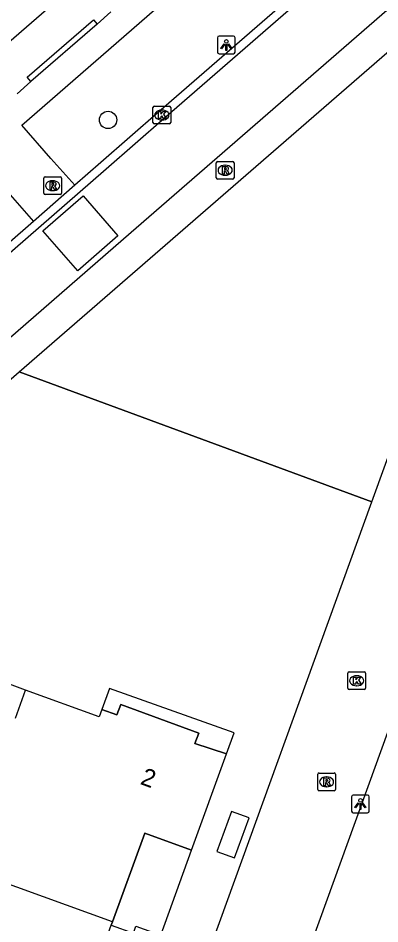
# Model space of a CAD drawing. Extents: x 155888 to 156864, y 383882 to 384671.
# Drawn here: x 156672 to 156692.5, y 384149.6 to 384200.8 of the extents above; entities that cross this region are included whole.
import ezdxf

# ---------------------------------------------------------------- set-up
doc = ezdxf.new("R2010")
doc.units = 0
for name, color, linetype in [('IMGEO_Boom', 7, 'Continuous'), ('IMGEO_Groenvoorziening', 7, 'Continuous'), ('IMGEO_Hek', 7, 'Continuous'), ('IMGEO_Kolk', 7, 'Continuous'), ('IMGEO_Lichtpunt', 7, 'Continuous'), ('IMGEO_Muur', 7, 'Continuous'), ('IMGEO_Pand', 7, 'Continuous'), ('IMGEO_Pand_nummerreeks', 7, 'Continuous'), ('IMGEO_Pand_overbouw', 7, 'Continuous'), ('IMGEO_Rijbaan_lokaal_gesloten', 7, 'Continuous'), ('IMGEO_Rijbaan_lokaal_open', 7, 'Continuous'), ('IMGEO_Rioolput', 7, 'Continuous'), ('IMGEO_Voetpad_open', 7, 'Continuous')]:
    doc.layers.add(name, color=color, linetype=linetype)

msp = doc.modelspace()

# ---------------------------------------------------------------- linework, layer by layer
at = {"layer": 'IMGEO_Boom'}
msp.add_circle((156677.091, 384195.006), 0.489, dxfattribs=at)
at = {"layer": 'IMGEO_Groenvoorziening'}
msp.add_lwpolyline([(156692.007, 384173.426), (156672.069, 384180.768)], dxfattribs=at)
at = {"layer": 'IMGEO_Hek'}
msp.add_lwpolyline([(156672.069, 384180.768), (156692.007, 384173.426)], dxfattribs=at)
at = {"layer": 'IMGEO_Kolk'}
for p, q in [((156679.631, 384194.856), (156679.631, 384195.708)), ((156679.706, 384195.782), (156680.558, 384195.782)), ((156680.119, 384195.562), (156680.144, 384195.562)), ((156680.632, 384195.708), (156680.632, 384194.856)), ((156680.142, 384195.002), (156680.117, 384195.002)), ((156680.558, 384194.782), (156679.706, 384194.782)), ((156690.645, 384162.902), (156690.645, 384163.754)), ((156690.72, 384163.828), (156691.572, 384163.828)), ((156691.646, 384163.754), (156691.646, 384162.902)), ((156691.133, 384163.608), (156691.158, 384163.608)), ((156691.572, 384162.828), (156690.72, 384162.828)), ((156691.156, 384163.048), (156691.131, 384163.048))]:
    msp.add_line(p, q, dxfattribs=at)
for points in [[(156679.631, 384194.856), (156679.631, 384195.708)], [(156679.706, 384195.782), (156680.558, 384195.782)], [(156679.952, 384195.482), (156680.075, 384195.482), (156680.075, 384195.331), (156680.205, 384195.482), (156680.369, 384195.482), (156680.223, 384195.331), (156680.376, 384195.082), (156680.224, 384195.082), (156680.139, 384195.246), (156680.075, 384195.179), (156680.075, 384195.082), (156679.952, 384195.082), (156679.952, 384195.482)], [(156680.632, 384195.708), (156680.632, 384194.856)], [(156680.558, 384194.782), (156679.706, 384194.782)], [(156690.645, 384162.902), (156690.645, 384163.754)], [(156690.72, 384163.828), (156691.572, 384163.828)], [(156691.646, 384163.754), (156691.646, 384162.902)], [(156690.966, 384163.528), (156691.089, 384163.528), (156691.089, 384163.377), (156691.219, 384163.528), (156691.383, 384163.528), (156691.237, 384163.377), (156691.39, 384163.128), (156691.238, 384163.128), (156691.153, 384163.292), (156691.089, 384163.225), (156691.089, 384163.128), (156690.966, 384163.128), (156690.966, 384163.528)], [(156691.572, 384162.828), (156690.72, 384162.828)]]:
    msp.add_lwpolyline(points, dxfattribs=at)
for centre, start, end in [((156679.708, 384195.706), 91.552, 178.448), ((156679.708, 384195.706), 91.552, 178.448), ((156680.556, 384195.706), 1.552, 88.448), ((156680.556, 384195.706), 1.552, 88.448), ((156679.708, 384194.858), 181.552, 268.448), ((156679.708, 384194.858), 181.552, 268.448), ((156680.556, 384194.858), 271.552, 358.448), ((156680.556, 384194.858), 271.552, 358.448), ((156690.722, 384163.752), 91.552, 178.448), ((156690.722, 384163.752), 91.552, 178.448), ((156691.57, 384163.752), 1.552, 88.448), ((156691.57, 384163.752), 1.552, 88.448), ((156690.722, 384162.904), 181.552, 268.448), ((156690.722, 384162.904), 181.552, 268.448), ((156691.57, 384162.904), 271.552, 358.448), ((156691.57, 384162.904), 271.552, 358.448)]:
    msp.add_arc(centre, 0.0765, start, end, dxfattribs=at)
for centre, major_axis, ratio, start_param, end_param in [((156680.118, 384195.282), (-0.387, 0.002), 0.722429, 4.712389, 7.853982), ((156680.143, 384195.282), (-0.39, 0.002), 0.717154, 1.570796, 4.712389), ((156691.132, 384163.328), (-0.387, 0.002), 0.722429, 4.712389, 7.853982), ((156691.157, 384163.328), (-0.39, 0.002), 0.717154, 1.570796, 4.712389)]:
    msp.add_ellipse(centre, major_axis=major_axis, ratio=ratio, start_param=start_param, end_param=end_param, dxfattribs=at)
at = {"layer": 'IMGEO_Lichtpunt'}
for p, q in [((156683.278, 384199.642), (156683.278, 384198.835)), ((156683.278, 384199.642), (156683.278, 384198.835)), ((156684.18, 384199.737), (156683.372, 384199.737)), ((156684.18, 384199.737), (156683.372, 384199.737)), ((156684.274, 384198.835), (156684.274, 384199.642)), ((156684.274, 384198.835), (156684.274, 384199.642)), ((156683.372, 384198.741), (156684.18, 384198.741)), ((156683.372, 384198.741), (156684.18, 384198.741)), ((156690.856, 384156.77), (156690.856, 384155.963)), ((156690.856, 384156.77), (156690.856, 384155.963)), ((156691.758, 384156.865), (156690.95, 384156.865)), ((156691.758, 384156.865), (156690.95, 384156.865)), ((156691.852, 384155.963), (156691.852, 384156.77)), ((156691.852, 384155.963), (156691.852, 384156.77)), ((156690.95, 384155.869), (156691.758, 384155.869)), ((156690.95, 384155.869), (156691.758, 384155.869))]:
    msp.add_line(p, q, dxfattribs=at)
for points in [[(156683.652, 384199.306), (156683.691, 384199.278), (156683.503, 384199.016), (156683.465, 384199.043), (156683.652, 384199.306)], [(156683.754, 384199.258), (156683.801, 384199.258), (156683.801, 384198.936), (156683.754, 384198.936), (156683.754, 384199.258)], [(156683.864, 384199.278), (156683.902, 384199.305), (156684.089, 384199.043), (156684.05, 384199.015), (156683.864, 384199.278)], [(156691.23, 384156.434), (156691.269, 384156.406), (156691.081, 384156.144), (156691.043, 384156.171), (156691.23, 384156.434)], [(156691.332, 384156.386), (156691.379, 384156.386), (156691.379, 384156.064), (156691.332, 384156.064), (156691.332, 384156.386)], [(156691.442, 384156.406), (156691.48, 384156.433), (156691.667, 384156.171), (156691.628, 384156.143), (156691.442, 384156.406)]]:
    msp.add_lwpolyline(points, dxfattribs=at)
for centre in [(156683.777, 384199.44), (156691.355, 384156.568)]:
    msp.add_circle(centre, 0.0994, dxfattribs=at)
for centre, start, end in [((156683.372, 384199.642), 90, 180), ((156683.372, 384199.642), 90, 180), ((156684.18, 384199.642), 0, 90), ((156684.18, 384199.642), 0, 90), ((156683.372, 384198.835), 180, 270), ((156683.372, 384198.835), 180, 270), ((156684.18, 384198.835), 270, 0), ((156684.18, 384198.835), 270, 360), ((156690.95, 384156.77), 90, 180), ((156690.95, 384156.77), 90, 180), ((156691.758, 384156.77), 0, 90), ((156691.758, 384156.77), 0, 90), ((156690.95, 384155.963), 180, 270), ((156690.95, 384155.963), 180, 270), ((156691.758, 384155.963), 270, 0), ((156691.758, 384155.963), 270, 360)]:
    msp.add_arc(centre, 0.0946, start, end, dxfattribs=at)
at = {"layer": 'IMGEO_Muur'}
for points in [[(156672.733, 384197.167), (156672.526, 384197.415), (156676.268, 384200.655), (156676.476, 384200.422)], [(156676.476, 384200.422), (156672.733, 384197.167)]]:
    msp.add_lwpolyline(points, dxfattribs=at)
at = {"layer": 'IMGEO_Pand'}
for points in [[(156669.908, 384198.049), (156674.33, 384201.888)], [(156672.432, 384162.801), (156671.665, 384163.081), (156670.901, 384163.359), (156670.316, 384161.754)], [(156671.86, 384161.221), (156672.432, 384162.801)], [(156677.346, 384149.719), (156679.164, 384154.728), (156681.815, 384153.766), (156683.784, 384159.195), (156681.996, 384159.791), (156682.227, 384160.372), (156677.806, 384161.995), (156677.585, 384161.395), (156676.734, 384161.702), (156676.583, 384161.289), (156672.432, 384162.801)], [(156685.065, 384155.579), (156684.064, 384155.942), (156683.245, 384153.687), (156684.246, 384153.323), (156685.065, 384155.579)], [(156677.346, 384149.719), (156668.027, 384153.076)], [(156665.166, 384142.801), (156669.32, 384141.3), (156669.171, 384140.885), (156670.058, 384140.55), (156669.843, 384139.968), (156674.219, 384138.355), (156674.438, 384138.969), (156676.213, 384138.331), (156678.183, 384143.76), (156675.532, 384144.722), (156676.281, 384146.785), (156677.274, 384149.521), (156677.346, 384149.719)]]:
    msp.add_lwpolyline(points, dxfattribs=at)
at = {"layer": 'IMGEO_Pand_overbouw'}
for points in [[(156676.734, 384161.702), (156677.585, 384161.395), (156677.806, 384161.995), (156682.227, 384160.372), (156681.996, 384159.791), (156683.784, 384159.195), (156684.214, 384160.381), (156677.165, 384162.89)], [(156681.815, 384153.766), (156679.164, 384154.728), (156677.346, 384149.719), (156677.274, 384149.521), (156678.524, 384149.067), (156678.67, 384149.47), (156680.071, 384148.963)]]:
    msp.add_lwpolyline(points, close=True, dxfattribs=at)
at = {"layer": 'IMGEO_Rijbaan_lokaal_gesloten'}
for points in [[(156801.435, 384295.362), (156777.585, 384274.792), (156749.039, 384250), (156728.765, 384232.392), (156677.961, 384188.273), (156649.173, 384163.247), (156638.782, 384153.801)], [(156634.485, 384156.375), (156635.856, 384157.199), (156636.046, 384156.976), (156642.257, 384162.207), (156643.817, 384163.481), (156671.684, 384187.621), (156676.99, 384192.247), (156680.268, 384195.108), (156710.742, 384221.573), (156715.95, 384226.1), (156723.484, 384232.637), (156743.439, 384250), (156749.57, 384255.335), (156754.859, 384259.931), (156761.065, 384265.282), (156788.507, 384289.088), (156788.213, 384289.442)]]:
    msp.add_lwpolyline(points, dxfattribs=at)
at = {"layer": 'IMGEO_Rijbaan_lokaal_open'}
for points in [[(156711.925, 384223.211), (156710.44, 384221.92), (156679.966, 384195.455), (156676.688, 384192.594), (156675.221, 384191.315)], [(156713.159, 384216.382), (156675.458, 384112.297)], [(156692.007, 384173.426), (156704.035, 384206.61), (156704.056, 384206.716)], [(156675.221, 384191.315), (156672.872, 384189.267)], [(156673.408, 384188.745), (156675.685, 384190.717), (156677.641, 384188.451), (156675.382, 384186.486), (156673.408, 384188.745)], [(156672.872, 384189.267), (156671.382, 384187.968), (156643.521, 384163.833), (156641.976, 384162.571), (156636.1, 384157.623), (156635.92, 384157.835)], [(156671.388, 384117.021), (156671.62, 384117.179), (156692.007, 384173.426)]]:
    msp.add_lwpolyline(points, dxfattribs=at)
at = {"layer": 'IMGEO_Rioolput'}
for p, q in [((156683.209, 384191.738), (156683.209, 384192.59)), ((156683.284, 384192.664), (156684.136, 384192.664)), ((156683.697, 384192.444), (156683.722, 384192.444)), ((156684.21, 384192.59), (156684.21, 384191.738)), ((156683.72, 384191.884), (156683.695, 384191.884)), ((156673.459, 384190.864), (156673.459, 384191.716)), ((156673.534, 384191.79), (156674.386, 384191.79)), ((156673.947, 384191.57), (156673.972, 384191.57)), ((156674.46, 384191.716), (156674.46, 384190.864)), ((156684.136, 384191.664), (156683.284, 384191.664)), ((156673.97, 384191.01), (156673.945, 384191.01)), ((156674.386, 384190.79), (156673.534, 384190.79)), ((156689.015, 384158.117), (156689.867, 384158.117)), ((156688.94, 384157.191), (156688.94, 384158.043)), ((156689.428, 384157.897), (156689.453, 384157.897)), ((156689.941, 384158.043), (156689.941, 384157.191)), ((156689.867, 384157.117), (156689.015, 384157.117)), ((156689.451, 384157.337), (156689.426, 384157.337))]:
    msp.add_line(p, q, dxfattribs=at)
for points in [[(156683.209, 384191.738), (156683.209, 384192.59)], [(156683.284, 384192.664), (156684.136, 384192.664)], [(156683.798, 384192.362), (156683.546, 384192.364), (156683.546, 384191.964)], [(156684.21, 384192.59), (156684.21, 384191.738)], [(156683.546, 384191.964), (156683.67, 384191.964), (156683.67, 384192.126), (156683.681, 384192.126)], [(156683.724, 384192.283), (156683.67, 384192.283), (156683.67, 384192.202)], [(156683.67, 384192.202), (156683.722, 384192.202)], [(156683.728, 384192.097), (156683.799, 384191.964), (156683.939, 384191.964), (156683.874, 384192.09)], [(156673.459, 384190.864), (156673.459, 384191.716)], [(156673.534, 384191.79), (156674.386, 384191.79)], [(156674.048, 384191.488), (156673.796, 384191.49), (156673.796, 384191.09)], [(156673.974, 384191.409), (156673.92, 384191.409), (156673.92, 384191.328)], [(156673.92, 384191.328), (156673.972, 384191.328)], [(156674.46, 384191.716), (156674.46, 384190.864)], [(156684.136, 384191.664), (156683.284, 384191.664)], [(156673.796, 384191.09), (156673.92, 384191.09), (156673.92, 384191.252), (156673.931, 384191.252)], [(156673.978, 384191.223), (156674.049, 384191.09), (156674.189, 384191.09), (156674.124, 384191.216)], [(156674.386, 384190.79), (156673.534, 384190.79)], [(156689.015, 384158.117), (156689.867, 384158.117)], [(156688.94, 384157.191), (156688.94, 384158.043)], [(156689.529, 384157.815), (156689.277, 384157.817), (156689.277, 384157.417)], [(156689.277, 384157.417), (156689.401, 384157.417), (156689.401, 384157.579), (156689.412, 384157.579)], [(156689.455, 384157.736), (156689.401, 384157.736), (156689.401, 384157.655)], [(156689.401, 384157.655), (156689.453, 384157.655)], [(156689.941, 384158.043), (156689.941, 384157.191)], [(156689.867, 384157.117), (156689.015, 384157.117)], [(156689.459, 384157.55), (156689.53, 384157.417), (156689.67, 384157.417), (156689.605, 384157.543)]]:
    msp.add_lwpolyline(points, dxfattribs=at)
for centre, radius, start, end in [((156683.286, 384192.588), 0.0765, 91.552, 178.448), ((156683.286, 384192.588), 0.0765, 91.552, 178.448), ((156683.797, 384192.252), 0.109, 350.3612, 89.416), ((156684.134, 384192.588), 0.0765, 1.552, 88.448), ((156684.134, 384192.588), 0.0765, 1.552, 88.448), ((156683.68, 384192.073), 0.0533, 26.0293, 88.6989), ((156683.706, 384192.391), 0.19, 274.7715, 282.9687), ((156683.73, 384192.187), 0.0964, 77.0061, 93.1865), ((156683.744, 384192.244), 0.0378, 276.6634, 79.6772), ((156683.795, 384192.252), 0.112, 277.5842, 350.9817), ((156683.779, 384192.037), 0.108, 29.5134, 73.7905), ((156673.536, 384191.714), 0.0765, 91.552, 178.448), ((156673.536, 384191.714), 0.0765, 91.552, 178.448), ((156673.956, 384191.517), 0.19, 274.7715, 282.9687), ((156673.98, 384191.313), 0.0964, 77.0061, 93.1865), ((156673.994, 384191.37), 0.0378, 276.6634, 79.6772), ((156674.047, 384191.378), 0.109, 350.3612, 89.416), ((156674.045, 384191.378), 0.112, 277.5842, 350.9817), ((156674.384, 384191.714), 0.0765, 1.552, 88.448), ((156674.384, 384191.714), 0.0765, 1.552, 88.448), ((156683.286, 384191.74), 0.0765, 181.552, 268.448), ((156683.286, 384191.74), 0.0765, 181.552, 268.448), ((156684.134, 384191.74), 0.0765, 271.552, 358.448), ((156684.134, 384191.74), 0.0765, 271.552, 358.448), ((156673.536, 384190.866), 0.0765, 181.552, 268.448), ((156673.536, 384190.866), 0.0765, 181.552, 268.448), ((156673.93, 384191.199), 0.0533, 26.0293, 88.6989), ((156674.029, 384191.163), 0.108, 29.5134, 73.7905), ((156674.384, 384190.866), 0.0765, 271.552, 358.448), ((156674.384, 384190.866), 0.0765, 271.552, 358.448), ((156689.017, 384158.041), 0.0765, 91.552, 178.448), ((156689.017, 384158.041), 0.0765, 91.552, 178.448), ((156689.865, 384158.041), 0.0765, 1.552, 88.448), ((156689.865, 384158.041), 0.0765, 1.552, 88.448), ((156689.411, 384157.526), 0.0533, 26.0293, 88.6989), ((156689.437, 384157.844), 0.19, 274.7715, 282.9687), ((156689.461, 384157.64), 0.0964, 77.0061, 93.1865), ((156689.475, 384157.697), 0.0378, 276.6634, 79.6772), ((156689.528, 384157.705), 0.109, 350.3612, 89.416), ((156689.526, 384157.705), 0.112, 277.5842, 350.9817), ((156689.51, 384157.49), 0.108, 29.5134, 73.7905), ((156689.017, 384157.193), 0.0765, 181.552, 268.448), ((156689.017, 384157.193), 0.0765, 181.552, 268.448), ((156689.865, 384157.193), 0.0765, 271.552, 358.448), ((156689.865, 384157.193), 0.0765, 271.552, 358.448)]:
    msp.add_arc(centre, radius, start, end, dxfattribs=at)
for centre, major_axis, ratio, start_param, end_param in [((156683.696, 384192.164), (-0.387, 0.002), 0.722429, 4.712389, 7.853982), ((156683.721, 384192.164), (-0.39, 0.002), 0.717154, 1.570796, 4.712389), ((156673.946, 384191.29), (-0.387, 0.002), 0.722429, 4.712389, 7.853982), ((156673.971, 384191.29), (-0.39, 0.002), 0.717154, 1.570796, 4.712389), ((156689.427, 384157.617), (-0.387, 0.002), 0.722429, 4.712389, 7.853982), ((156689.452, 384157.617), (-0.39, 0.002), 0.717154, 1.570796, 4.712389)]:
    msp.add_ellipse(centre, major_axis=major_axis, ratio=ratio, start_param=start_param, end_param=end_param, dxfattribs=at)
at = {"layer": 'IMGEO_Voetpad_open'}
for points in [[(156675.221, 384191.315), (156673.849, 384192.818), (156672.225, 384194.714), (156708.991, 384226.672), (156710.64, 384224.727), (156711.925, 384223.211)], [(156672.069, 384180.768), (156703.377, 384207.942)], [(156677.253, 384201.108), (156676.476, 384200.422)], [(156672.733, 384197.167), (156671.948, 384196.487)], [(156635.92, 384157.835), (156633.306, 384160.897), (156669.903, 384192.706), (156671.568, 384190.778), (156672.872, 384189.267)], [(156640.231, 384152.904), (156672.069, 384180.768)]]:
    msp.add_lwpolyline(points, dxfattribs=at)

# ---------------------------------------------------------------- texts
at = {"layer": 'IMGEO_Pand_nummerreeks'}
msp.add_text('2', height=1, rotation=339.7517, dxfattribs=at).set_placement((156678.861, 384157.507))

doc.saveas('drawing.dxf')
